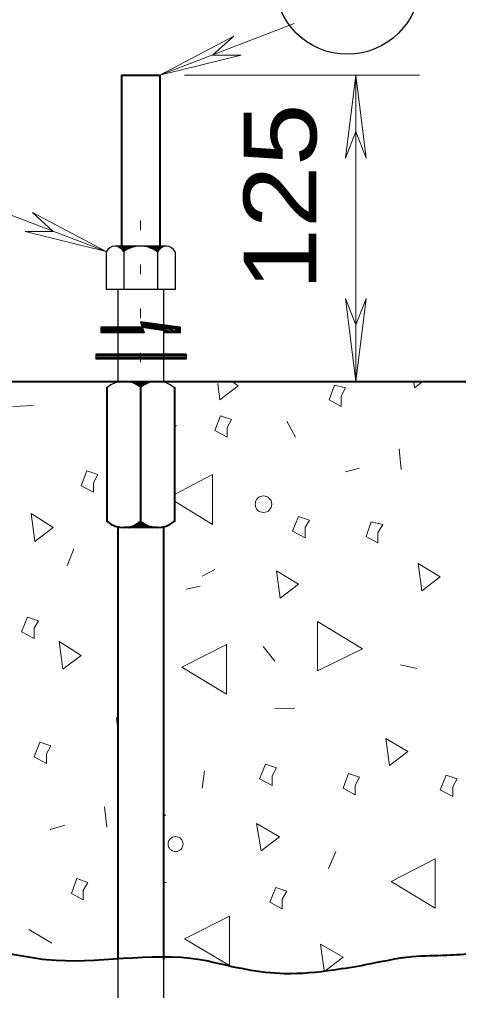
# Model space of a CAD drawing. Extents: x 312583 to 312854, y 144419 to 144597.
# Drawn here: x 312733.5 to 312738.09, y 144459.13 to 144469.26 of the extents above; entities that cross this region are included whole.
import ezdxf

# ---------------------------------------------------------------- set-up
doc = ezdxf.new("R2010")
doc.units = 0
doc.header["$LTSCALE"] = 0.3
doc.linetypes.add('DOTTED', pattern=[1.5, 0.3, -1.2])
doc.linetypes.add('SHORT_DASHED', pattern=[2.7, 1.5, -1.2])
doc.layers.add('1', color=7, linetype='Continuous', lineweight=25)
doc.layers.add('2', color=7, linetype='Continuous', lineweight=13)

msp = doc.modelspace()

# ---------------------------------------------------------------- linework, layer by layer
at = {"layer": '1', "lineweight": 40}
for p, q in [((312734.5682, 144468.6838), (312734.9669, 144468.6838)), ((312734.5682, 144468.6838), (312734.5682, 144466.8975)), ((312734.9669, 144468.6838), (312734.9669, 144466.8975)), ((312724.8622, 144465.4868), (312790.0289, 144465.4868)), ((312728.8566, 144465.4868), (312794.0232, 144465.4868)), ((312734.7676, 144465.4868), (312734.7676, 144463.9611)), ((312734.4149, 144465.4255), (312734.4149, 144464.0225)), ((312735.1202, 144465.4255), (312735.1202, 144464.0225)), ((312734.5299, 144463.9611), (312734.5299, 144459.4531)), ((312734.9439, 144463.9611), (312734.5912, 144463.9611)), ((312735.0052, 144463.9611), (312735.0052, 144459.4531))]:
    msp.add_line(p, q, dxfattribs=at)
at = {"layer": '1', "linetype": 'DOTTED', "lineweight": 13}
msp.add_line((312734.7676, 144467.1658), (312734.7676, 144465.4868), dxfattribs=at)
at = {"layer": '1'}
for p, q in [((312735.0359, 144466.8975), (312734.4992, 144466.8975)), ((312734.4072, 144466.8438), (312734.4072, 144466.4451)), ((312734.5912, 144466.8438), (312734.5912, 144466.4451)), ((312734.9439, 144466.8438), (312734.9439, 144466.4451)), ((312735.1279, 144466.8438), (312735.1279, 144466.4451)), ((312735.1279, 144466.4451), (312734.4072, 144466.4451)), ((312734.5299, 144466.4451), (312734.5299, 144465.4868)), ((312735.0052, 144466.4451), (312735.0052, 144465.4868)), ((312734.3536, 144466.0541), (312734.3536, 144465.9928)), ((312734.7829, 144466.0541), (312734.3536, 144466.0541)), ((312734.8059, 144465.9928), (312734.3536, 144465.9928)), ((312735.1816, 144466.0541), (312735.1816, 144465.9928)), ((312735.2429, 144465.7705), (312734.2999, 144465.7705)), ((312734.2999, 144465.7705), (312734.2999, 144465.7168)), ((312735.2429, 144465.7705), (312735.2429, 144465.7168)), ((312735.2429, 144465.7551), (312734.2999, 144465.7551)), ((312735.2429, 144465.7398), (312734.2999, 144465.7398)), ((312735.2429, 144465.7245), (312734.2999, 144465.7245)), ((312735.2429, 144465.7168), (312734.2999, 144465.7168)), ((312735.0052, 144465.4868), (312734.5299, 144465.4868)), ((312734.9439, 144465.4868), (312734.5912, 144465.4868))]:
    msp.add_line(p, q, dxfattribs=at)
at = {"layer": '1', "linetype": 'SHORT_DASHED'}
for p, q in [((312734.5299, 144459.4531), (312734.5299, 144457.6591)), ((312735.0052, 144459.4531), (312735.0052, 144457.1838))]:
    msp.add_line(p, q, dxfattribs=at)
at = {"layer": '1'}
for points in [[(312734.5222, 144466.8975), (312734.7216, 144466.8975), (312734.6909, 144466.8898), (312734.6679, 144466.8821), (312734.6296, 144466.8668), (312734.5912, 144466.8438), (312734.5759, 144466.8668), (312734.5606, 144466.8821), (312734.5299, 144466.8975), (312734.7062, 144466.8975), (312734.6602, 144466.8821), (312734.6219, 144466.8668), (312734.5912, 144466.8515), (312734.5606, 144466.8745), (312734.5452, 144466.8898), (312734.6832, 144466.8898), (312734.6372, 144466.8745), (312734.5912, 144466.8515), (312734.5529, 144466.8898), (312734.6679, 144466.8898), (312734.5912, 144466.8591), (312734.5606, 144466.8898), (312734.6526, 144466.8898), (312734.5912, 144466.8668), (312734.5682, 144466.8821), (312734.6449, 144466.8821), (312734.5912, 144466.8668), (312734.5759, 144466.8821), (312734.6219, 144466.8821), (312734.5912, 144466.8745), (312734.5836, 144466.8821), (312734.6066, 144466.8821), (312734.5912, 144466.8745)], [(312735.0129, 144466.8975), (312734.8136, 144466.8975), (312734.8519, 144466.8898), (312734.8672, 144466.8821), (312734.9056, 144466.8668), (312734.9439, 144466.8438), (312734.9592, 144466.8668), (312734.9746, 144466.8821), (312735.0052, 144466.8975), (312734.8289, 144466.8975), (312734.8826, 144466.8821), (312734.9132, 144466.8668), (312734.9439, 144466.8515), (312734.9746, 144466.8745), (312734.9899, 144466.8898), (312734.8519, 144466.8898), (312734.8979, 144466.8745), (312734.9439, 144466.8515), (312734.9822, 144466.8898), (312734.8672, 144466.8898), (312734.9439, 144466.8591), (312734.9746, 144466.8898), (312734.8826, 144466.8898), (312734.9516, 144466.8668), (312734.9669, 144466.8821), (312734.8979, 144466.8821), (312734.9439, 144466.8668), (312734.9592, 144466.8821), (312734.9132, 144466.8821), (312734.9439, 144466.8745), (312734.9516, 144466.8821), (312734.9286, 144466.8821), (312734.9439, 144466.8745)], [(312735.1816, 144466.0541), (312734.7676, 144466.1078), (312734.8059, 144465.9928)], [(312735.0052, 144465.9928), (312735.1816, 144466.0005), (312735.1739, 144466.0465), (312734.7829, 144466.1001), (312734.7906, 144466.0541), (312735.0129, 144466.0235), (312735.0129, 144466.0005), (312735.1739, 144466.0081), (312735.1739, 144466.0388), (312734.7906, 144466.0925), (312734.7982, 144466.0618), (312735.0206, 144466.0235), (312735.0206, 144466.0081), (312735.1662, 144466.0158), (312735.1662, 144466.0311), (312734.8059, 144466.0848), (312734.8059, 144466.0695), (312735.0206, 144466.0311), (312735.0282, 144466.0235), (312735.0742, 144466.0158), (312735.1586, 144466.0235), (312734.8136, 144466.0771), (312735.1049, 144466.0235)], [(312734.7906, 144466.0005), (312734.3612, 144466.0005), (312734.3612, 144466.0465), (312734.7752, 144466.0465), (312734.7906, 144466.0081), (312734.3689, 144466.0081), (312734.3689, 144466.0388), (312734.7752, 144466.0311), (312734.7829, 144466.0158), (312734.3766, 144466.0158), (312734.3842, 144466.0311), (312734.3842, 144466.0311), (312734.7676, 144466.0311), (312734.7752, 144466.0235), (312734.3842, 144466.0235)], [(312734.7829, 144466.0541), (312735.1816, 144465.9928), (312735.0052, 144465.9928)], [(312734.8979, 144465.4868), (312734.6372, 144465.4868), (312734.6679, 144465.4791), (312734.6986, 144465.4715), (312734.7216, 144465.4561), (312734.7446, 144465.4485), (312734.7676, 144465.4331), (312734.7676, 144465.4255), (312734.8136, 144465.4638), (312734.8596, 144465.4791), (312734.8826, 144465.4868), (312734.6526, 144465.4868), (312734.6756, 144465.4791), (312734.6986, 144465.4791), (312734.7216, 144465.4638), (312734.7522, 144465.4485), (312734.7599, 144465.4408), (312734.7676, 144465.4331), (312734.8136, 144465.4638), (312734.8596, 144465.4791), (312734.6909, 144465.4791), (312734.7292, 144465.4638), (312734.7676, 144465.4408), (312734.8442, 144465.4791), (312734.7062, 144465.4791), (312734.7676, 144465.4408), (312734.8289, 144465.4715), (312734.7216, 144465.4791), (312734.7676, 144465.4485), (312734.8059, 144465.4715), (312734.7369, 144465.4715), (312734.7676, 144465.4638), (312734.8059, 144465.4715), (312734.7829, 144465.4561), (312734.7752, 144465.4715), (312734.7676, 144465.4485), (312734.7522, 144465.4638), (312734.7446, 144465.4638), (312734.7292, 144465.4715)]]:
    msp.add_lwpolyline(points, dxfattribs=at)
at = {"layer": '1', "lineweight": 40}
msp.add_lwpolyline([(312734.8979, 144463.9611), (312734.6372, 144463.9611), (312734.6679, 144463.9688), (312734.6986, 144463.9765), (312734.7216, 144463.9918), (312734.7446, 144463.9995), (312734.7676, 144464.0148), (312734.7676, 144464.0225), (312734.8136, 144463.9841), (312734.8596, 144463.9688), (312734.8826, 144463.9688), (312734.6526, 144463.9611), (312734.6756, 144463.9688), (312734.6986, 144463.9688), (312734.7216, 144463.9841), (312734.7522, 144463.9995), (312734.7599, 144464.0071), (312734.7676, 144464.0148), (312734.8136, 144463.9841), (312734.8596, 144463.9688), (312734.6909, 144463.9688), (312734.7292, 144463.9841), (312734.7676, 144464.0071), (312734.8442, 144463.9688), (312734.7062, 144463.9688), (312734.7676, 144464.0071), (312734.8289, 144463.9765), (312734.7216, 144463.9688), (312734.7676, 144463.9995), (312734.8059, 144463.9765), (312734.7369, 144463.9765), (312734.7676, 144463.9841), (312734.8059, 144463.9841), (312734.7829, 144463.9918), (312734.7752, 144463.9765), (312734.7676, 144463.9995), (312734.7522, 144463.9841), (312734.7446, 144463.9841), (312734.7292, 144463.9765)], dxfattribs=at)
at = {"layer": '1'}
for centre, radius, start, end in [((312734.4996, 144466.7979), 0.0993, 25.60064, 154.39936), ((312734.7682, 144466.5846), 0.3126, 55.04559, 124.95441), ((312735.0368, 144466.7979), 0.0993, 25.60064, 154.39936), ((312734.5934, 144465.2153), 0.272, 50.00693, 129.99306), ((312734.943, 144465.2153), 0.272, 50.00694, 129.99307)]:
    msp.add_arc(centre, radius, start, end, dxfattribs=at)
at = {"layer": '1', "lineweight": 40}
for centre, start, end in [((312734.5934, 144464.2327), 230.00694, 309.99307), ((312734.943, 144464.2327), 230.00693, 309.99306)]:
    msp.add_arc(centre, 0.272, start, end, dxfattribs=at)
for points in [[(312729.7536, 144465.4715), (312729.9529, 144464.8505), (312730.0449, 144462.2438), (312730.4972, 144461.5461), (312731.0109, 144461.0861), (312731.5782, 144460.5725), (312732.2759, 144460.0128), (312732.7052, 144459.6065), (312733.1116, 144459.5528), (312733.7862, 144459.4531), (312735.3886, 144459.4531), (312735.4729, 144459.4378)], [(312735.4729, 144459.4378), (312736.2702, 144459.3075), (312736.7839, 144459.3458), (312737.1136, 144459.3995), (312737.6042, 144459.4838), (312737.9646, 144459.4991), (312738.2406, 144459.5145), (312738.5396, 144459.5375), (312738.8156, 144459.6371), (312739.0072, 144459.7751)]]:
    msp.add_spline(points, degree=3, dxfattribs=at)
at = {"layer": '2'}
for p, q in [((312736.3699, 144469.2205), (312734.9669, 144468.6838)), ((312734.9669, 144468.6838), (312735.7412, 144469.0901)), ((312735.7412, 144469.0901), (312735.5189, 144468.8908)), ((312734.9669, 144468.6838), (312735.8179, 144468.8908)), ((312735.8179, 144468.8908), (312735.5189, 144468.8908)), ((312737.6791, 144468.6838), (312735.2276, 144468.6838)), ((312737.015, 144468.6838), (312736.9077, 144467.8175)), ((312737.015, 144465.4868), (312737.015, 144468.6838)), ((312737.015, 144468.6838), (312737.1223, 144467.8175)), ((312736.9077, 144467.8175), (312737.015, 144468.0935)), ((312737.1223, 144467.8175), (312737.015, 144468.0935)), ((312733.0349, 144467.3651), (312734.4072, 144466.8438)), ((312733.6406, 144467.2501), (312733.8552, 144467.0508)), ((312734.4072, 144466.8438), (312733.6406, 144467.2501)), ((312733.5639, 144467.0508), (312733.8552, 144467.0508)), ((312734.4072, 144466.8438), (312733.5639, 144467.0508)), ((312736.9077, 144466.3531), (312737.015, 144466.0771)), ((312737.015, 144465.4868), (312736.9077, 144466.3531)), ((312737.1223, 144466.3531), (312737.015, 144466.0771)), ((312737.015, 144465.4868), (312737.1223, 144466.3531)), ((312735.5726, 144465.4638), (312735.5956, 144465.2951)), ((312737.6196, 144465.4791), (312737.6272, 144465.4178)), ((312737.6272, 144465.4178), (312737.7039, 144465.4791)), ((312733.4336, 144465.2261), (312733.6482, 144465.2338)), ((312736.2932, 144465.0728), (312736.3852, 144464.9041)), ((312735.1432, 144465.0268), (312735.1202, 144465.0115)), ((312737.4662, 144464.7815), (312737.4892, 144464.5668)), ((312736.9066, 144464.5438), (312737.0522, 144464.5821)), ((312735.1202, 144464.2371), (312735.5189, 144463.9918)), ((312734.0699, 144463.7388), (312734.0009, 144463.5625)), ((312735.4116, 144463.4551), (312735.5419, 144463.5241)), ((312735.2429, 144463.3171), (312735.3886, 144463.3478)), ((312736.0479, 144462.7191), (312736.1706, 144462.5658)), ((312737.4816, 144462.5275), (312737.6502, 144462.4891)), ((312736.1706, 144462.0675), (312736.3776, 144462.0751)), ((312735.4116, 144461.2395), (312735.4346, 144461.4235)), ((312734.3919, 144461.0478), (312734.4149, 144460.8331)), ((312733.8246, 144460.8101), (312733.9779, 144460.8561)), ((312736.8069, 144460.5801), (312736.7302, 144460.4038)), ((312735.0052, 144460.2581), (312735.0359, 144460.2581)), ((312733.8399, 144459.6218), (312733.6022, 144459.7675))]:
    msp.add_line(p, q, dxfattribs=at)
for points in [[(312735.5956, 144465.2951), (312735.7872, 144465.4408), (312735.7412, 144465.4715)], [(312735.5189, 144463.9918), (312735.5189, 144464.5131), (312735.1202, 144464.3061)], [(312735.0052, 144462.8648), (312735.0129, 144462.8725), (312735.0052, 144462.8725)], [(312734.5299, 144461.9678), (312734.5146, 144461.9755), (312734.5299, 144461.8528)], [(312735.0052, 144460.9481), (312735.0282, 144460.9558), (312735.0052, 144460.9711)], [(312736.7072, 144459.3458), (312736.8836, 144459.4761), (312736.6459, 144459.6141), (312736.6842, 144459.3381)]]:
    msp.add_lwpolyline(points, dxfattribs=at)
for points in [[(312736.8606, 144465.3335), (312736.9066, 144465.4178), (312736.7916, 144465.4485), (312736.7379, 144465.2951), (312736.8606, 144465.2261)], [(312735.6722, 144465.0038), (312735.7182, 144465.0881), (312735.6032, 144465.1265), (312735.5419, 144464.9731), (312735.6722, 144464.9041)], [(312734.2769, 144464.4288), (312734.3229, 144464.5131), (312734.2079, 144464.5515), (312734.1466, 144464.3981), (312734.2769, 144464.3291)], [(312733.6636, 144463.8155), (312733.8552, 144463.9611), (312733.6252, 144464.1068)], [(312736.4849, 144463.9611), (312736.5309, 144464.0378), (312736.4159, 144464.0761), (312736.3546, 144463.9228), (312736.4849, 144463.8538)], [(312737.2439, 144463.9075), (312737.2976, 144463.9918), (312737.1749, 144464.0225), (312737.1212, 144463.8691), (312737.2439, 144463.8001)], [(312737.7039, 144463.3018), (312737.8956, 144463.4475), (312737.6656, 144463.5855)], [(312736.2242, 144463.2251), (312736.4159, 144463.3708), (312736.1859, 144463.5088)], [(312733.6559, 144462.9108), (312733.7019, 144462.9875), (312733.5869, 144463.0258), (312733.5256, 144462.8725), (312733.6559, 144462.8035)], [(312736.6152, 144462.9798), (312736.6152, 144462.4661), (312737.0829, 144462.6961)], [(312733.9549, 144462.4815), (312734.1466, 144462.6271), (312733.9166, 144462.7728)], [(312735.6646, 144462.2208), (312735.6646, 144462.7421), (312735.1969, 144462.5045)], [(312733.7862, 144461.5998), (312733.8322, 144461.6841), (312733.7172, 144461.7225), (312733.6559, 144461.5691), (312733.7862, 144461.5001)], [(312737.3666, 144461.4771), (312737.5582, 144461.6228), (312737.3282, 144461.7608)], [(312736.1399, 144461.3698), (312736.1859, 144461.4541), (312736.0709, 144461.4925), (312736.0096, 144461.3391), (312736.1399, 144461.2701)], [(312737.0062, 144461.2701), (312737.0522, 144461.3545), (312736.9372, 144461.3928), (312736.8836, 144461.2395), (312737.0062, 144461.1705)], [(312738.0259, 144461.2548), (312738.0719, 144461.3391), (312737.9569, 144461.3775), (312737.8956, 144461.2241), (312738.0259, 144461.1551)], [(312736.0249, 144460.5878), (312736.2166, 144460.7335), (312735.9789, 144460.8715)], [(312737.8419, 144459.9898), (312737.8419, 144460.5035), (312737.3819, 144460.2658)], [(312734.1696, 144460.1738), (312734.2156, 144460.2581), (312734.1006, 144460.2965), (312734.0469, 144460.1431), (312734.1696, 144460.0741)], [(312736.2472, 144460.0818), (312736.2932, 144460.1661), (312736.1782, 144460.2045), (312736.1169, 144460.0511), (312736.2472, 144459.9821)], [(312735.6952, 144459.3918), (312735.6952, 144459.9055), (312735.2276, 144459.6678)]]:
    msp.add_lwpolyline(points, close=True, dxfattribs=at)
at = {"layer": '2', "lineweight": 25}
msp.add_circle((312736.9271, 144469.6558), 0.7557, dxfattribs=at)
at = {"layer": '2'}
for centre, radius in [((312736.0502, 144464.2048), 0.0865), ((312735.1327, 144460.658), 0.0784)]:
    msp.add_circle(centre, radius, dxfattribs=at)

# ---------------------------------------------------------------- texts
at = {"layer": '2', "width": 1.15}
msp.add_text('125 ', height=0.76, rotation=90, dxfattribs=at).set_placement((312736.603, 144466.4363))

doc.saveas('drawing.dxf')
